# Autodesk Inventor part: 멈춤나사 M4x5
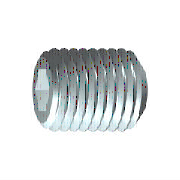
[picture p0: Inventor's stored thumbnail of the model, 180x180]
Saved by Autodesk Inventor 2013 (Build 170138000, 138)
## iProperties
IsCustomPart: 1
Created: 2012-02
Part Number: 멈춤나사 M4x5
Material: 강철, 연강
Description: 6각 소켓 머리 없는 멈춤 나사
Document SubType Name: Modeling
Standard: KS B 1028
Designer: mduedu
Standards Organization: KS
Language: ko-KR
Size Designation: 납작점M4x5
Categories: <MemberInstance><Categories><Category DisplayName="조임쇠" InternalName="e4da775c-781d-43d5-af7c-5136215cf5a6" Mnemonic="FSTN"><Category DisplayName="볼트" InternalN
Density: 1 g/cm^3
Author: mduedu
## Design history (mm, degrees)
sketch "스케치1"
  geometry: L1 (0, 0)-(1.833, 0); L2 (5, 1.155)-(5, 2); L3 (5, 2)-(0, 2); L4 (5, 1.155)-(2.5, 1.155); L5 (2.5, 1.155)-(1.833, 0); L6 (0, -0.4)-(0, 2.4) reference; L7 (0, 2)-(0, 0)
  constraints: 13 end point, 3 parallel, 1 collinear, 1 perpendicular, 1 point on line
  dimensions: "d0" = 2.5 distance of L2.start L4.end (= INTI); "d1" = 60 deg angle of L5 L1; "d2" = 4 diameter of L3 L1 (= NND); "d3" = 2.3094 diameter of L4 L1 (= 1.1547 x SW); "d5" = 5 distance from line of L2 L3.end (= NLG)
revolve "본체" sketch "스케치1" stored, may be unused: angle "d6" = 90 deg
sketch "스케치2"
  geometry: L1 (-0.577, 1)-(0.577, 1); L2 (0.577, 1)-(1.155, 0); L3 (1.155, 0)-(0.577, -1); L4 (0.577, -1)-(-0.577, -1); L5 (-0.577, -1)-(-1.155, 0); L6 (-1.155, 0)-(-0.577, 1); A1 r 1.155 centre (0, 0) between (-0.577, 1) and (0.577, 1) reference; 2 further points
  constraints: 12 end point, 2 point on circle, 1 coincident, 1 horizontal, 11 other
extrude "슬롯" join sketch "스케치2" taper "d9" = 0 deg; stored distance "d21" = 10
workaxis "Work Axis1"
workplane "Work Plane1"
body "Solid1"
chamfer "모따기1" distance "d7" = 0.42941 (= -0.5 x GD1 + 0.5 x NND); stored, may be unused: angle "d8" = 45 deg (= FAWI), second distance "d29" = 0.42941 (= -0.5 x GD1 + 0.5 x NND)
feature "스레드" dims "d11" = 5 (= NLG), "d12" = 0
chamfer "모따기2" distance "d13" = 0.42941 (= -0.5 x GD1 + 0.5 x NND); stored, may be unused: angle "d14" = 45 deg (= FAWI), second distance "d30" = 0.42941 (= -0.5 x GD1 + 0.5 x NND)
other parameters: "NND" = 4 [user parameter; used in 5 equation terms], "NLG" = 5 [user parameter; used in 2 equation terms], "INTI" = 2.5 [user parameter; used in 1 equation term], "FAWI" = 45 deg [user parameter; used in 2 equation terms], "SW" = 2 [user parameter; used in 2 equation terms], "GD1" = 3.14117 (= THREADDIA - 1.2269 x PTC) [user parameter; used in 4 equation terms], "d4" = 0, "FAWI1" = 45 deg [user parameter], "d15" = 0, "d31" = 0, "GUL" = 0.42941 (= 0.61345 x PTC) [user parameter], "SPD" = 2.5 [user parameter], "TPU" = 14.28571 (computed from PTC) [user parameter], "TOA" = 30 deg [user parameter], "THREADDIA" = 4 [user parameter; used in 1 equation term], "PTC" = 0.7 [user parameter; used in 4 equation terms], "GAL" = 0.42941 (= 0.61345 x PTC) [user parameter], "E0" = 2.31 (= 1.155 x SW) [user parameter]
